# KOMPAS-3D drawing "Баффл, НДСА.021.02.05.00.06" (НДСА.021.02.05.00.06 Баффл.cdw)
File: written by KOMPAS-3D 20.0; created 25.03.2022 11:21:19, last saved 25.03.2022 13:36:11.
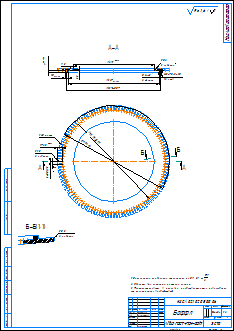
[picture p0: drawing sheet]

Sheet 1: A2, portrait

Document properties: Автор: adminzsc; Знак неуказанной шероховатости: 4; Параметр неуказанной шероховатости: Ra 1,6; PLM_CDWXDTO: <item xmlns="http://appius.ru/pdm" xmlns:xs="http://www.w3.org/2001/XMLSchema" xmlns:xsi="http://www.w3.org/2001/XMLSchema-instance" xsi:type="item">  <element xmlns:d2p1="http://v8.1c.ru/8.1/data/enterprise/current-config" xsi:type="d2p1:CatalogRef.aps_Элемен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; Масса: 1.16448; PDM_DOCXDTO: <item xmlns="http://appius.ru/pdm" xmlns:xs="http://www.w3.org/2001/XMLSchema" xmlns:xsi="http://www.w3.org/2001/XMLSchema-instance" xsi:type="item">  <element xmlns:d2p1="http://v8.1c.ru/8.1/data/enterprise/current-config" xsi:type="d2p1:CatalogRef.aps_Элемен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; PDM_ITEMXDTO: <item xmlns="http://appius.ru/pdm" xmlns:xs="http://www.w3.org/2001/XMLSchema" xmlns:xsi="http://www.w3.org/2001/XMLSchema-instance" xsi:type="item">  <element xmlns:d2p1="http://v8.1c.ru/8.1/data/enterprise/current-config" xsi:type="d2p1:CatalogRef.aps_Элемен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; PDM_DRAWINGXDTO: <item xmlns="http://appius.ru/pdm" xmlns:xs="http://www.w3.org/2001/XMLSchema" xmlns:xsi="http://www.w3.org/2001/XMLSchema-instance" xsi:type="item">  <element xmlns:d2p1="http://v8.1c.ru/8.1/data/enterprise/current-config" xsi:type="d2p1:CatalogRef.aps_Элемен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

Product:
- Part/product: Баффл  | designation НДСА.021.02.05.00.06
    Материал: АМг6  ГОСТ 4784-2019 (density 2640 kg/m3)
    Масса: 1.16448
    additional columns: <item xmlns="http://appius.ru/pdm" xmlns:xs="http://www.w3.org/2001/XMLSchema" x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; <item xmlns="http://appius.ru/pdm" xmlns:xs="http://www.w3.org/2001/XMLSchema" x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; <item xmlns="http://appius.ru/pdm" xmlns:xs="http://www.w3.org/2001/XMLSchema" x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
    source file: НДСА.021.02.05.00.06 Баффл.cdw

Title block, sheet 1: Наименование: Баффл; designation: НДСА.021.02.05.00.06; Материал: АМг6  ГОСТ 4784-2019; Масса: 1164,48 г; Количество листов документа: 1; organisation: ЭСТО; Форматы листов документа: A2; stored path: C:\Users\vasilyeva\Desktop\PM_APPIUS\НДСА.021.02.05.00.06 Баффл.cdw; Разработал: Васильева; Проверил: Горностаев; Утвердил: Белецкий; Разработал, date: 25.03.2022

Views: Разрез А-А, Разрез Б-Б
Referenced files in C:\Users\vasilyeva\Desktop\: НДСА.021.02.05.00.06 Баффл.m3d
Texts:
  JS9
  М5-7Нх8-10
  Ra 1,6
  Ra 1,6 ( )
  НДСА.021.02.05.00.06 Баффл
Dimensions and other numbers on the sheet: 291; 9,5; 3,5; 327; 10; 337±0,07; 7; 12 отв.; 0,3; 2 фаски; 0,2; 3 радиуса; 0,5; 2 радиуса; 1:2; 1; 1164,48 г; 25.03.2022

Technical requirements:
  Неуказанные предельные откланения по H9, h9,    IT9 2 .
  Удалить все заусенцы и острые кромки;
  Транспортировать в упаковке, предотвращающая повреждения
  от механических воздействий.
